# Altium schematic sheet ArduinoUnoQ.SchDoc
size A4; SheetNumber: 1; SheetTotal: 1
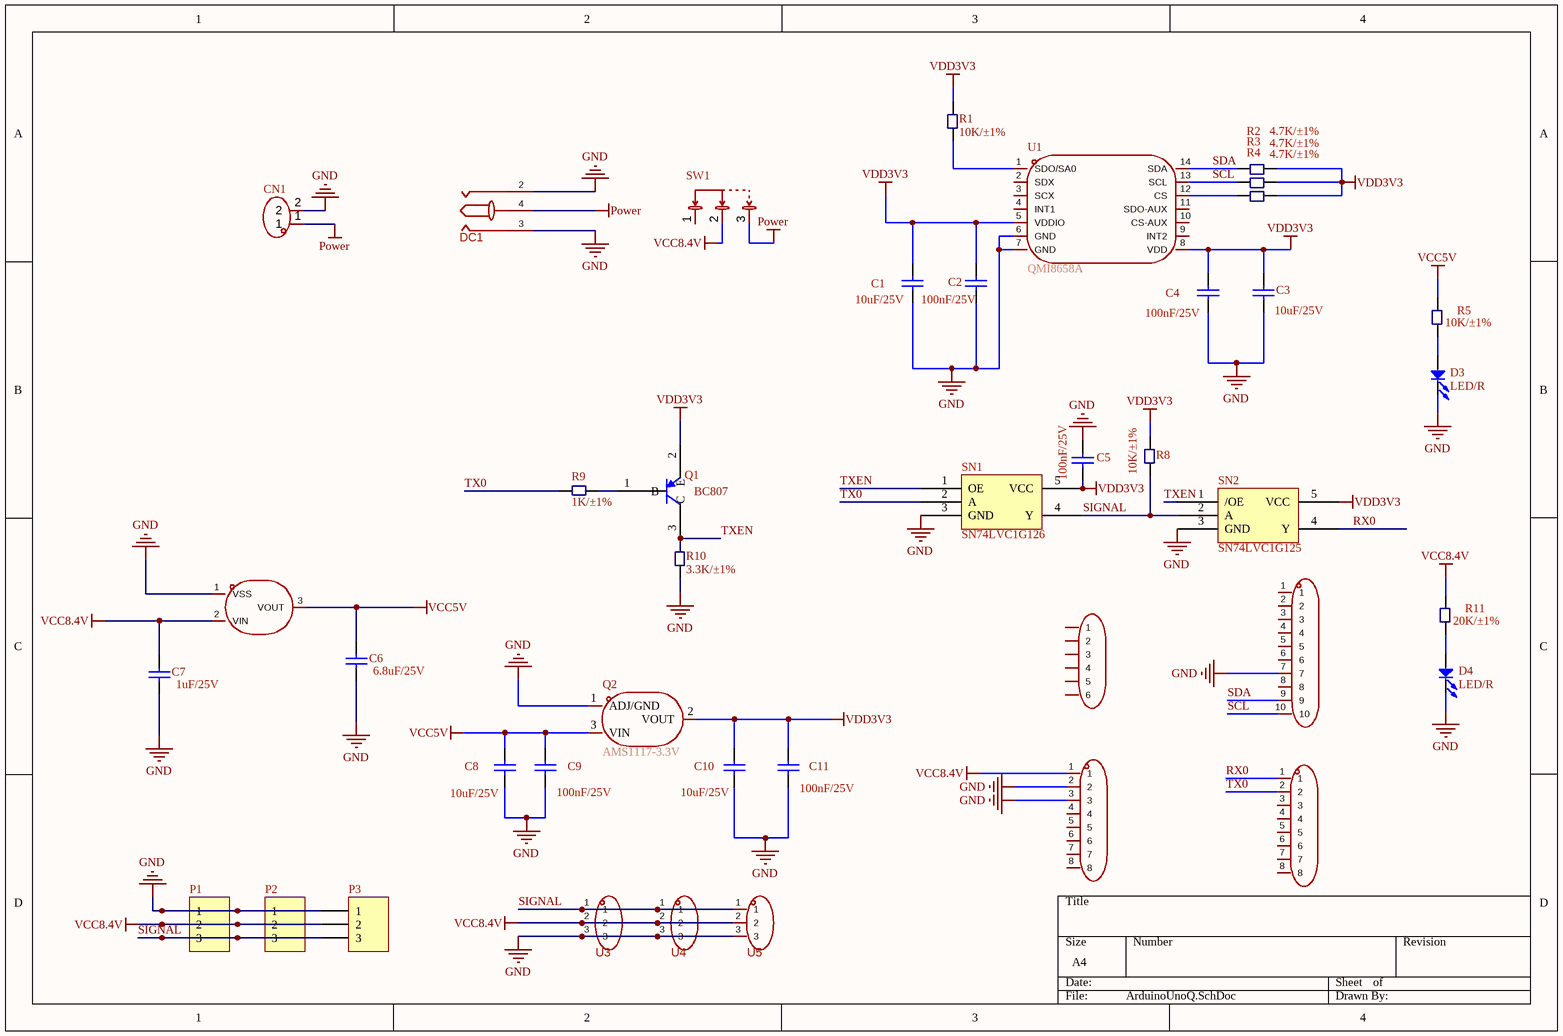
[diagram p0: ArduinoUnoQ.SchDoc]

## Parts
C1  10uF/25V  [C0603]
C2  100nF/25V  [C0603]
C3  10uF/25V  [C0603]
C4  100nF/25V  [C0603]
C5  100nF/25V  [C0603]
C6  6.8uF/25V  [C0603]
C7  1uF/25V  [C0603]
C8  10uF/25V  [C0603]
C9  100nF/25V  [C0603]
C10  10uF/25V  [C0603]
C11  100nF/25V  [C0603]
CN1  ZX-XH2.54-2PWZ  [CONN-TH_2P-P2.50_ZX-XH2.54-2PWZ]  (value not drawn)
D3  LED/R  [D_SOD_523]
D4  LED/R  [D_SOD_523]
DC1  kh-dc-007b-2.1g  [DC-IN-TH_KH-DC-007B-2.1G]  (value not drawn)
H1  pz254v-11-06p  [HDR-TH_6P-P2.54-V-M]  (value not drawn)
H2  pz254v-11-10p  [HDR-TH_10P-P2.54-V-M]  (value not drawn)
H3  pz254v-11-08p  [HDR-TH_8P-P2.54-V-M]  (value not drawn)
H4  pz254v-11-08p  [HDR-TH_8P-P2.54-V-M]  (value not drawn)
P1  mx1.25 1*3P  [MX 1.25-WI-3P]  (value not drawn)
P2  mx1.25 1*3P  [MX 1.25-WI-3P]  (value not drawn)
P3  mx1.25 1*3P  [MX 1.25-WI-3P]  (value not drawn)
Q1  BC807  [SOT-23-3]
Q2  AMS1117-3.3V  [SOT-89-3_L4.5-W2.5-P1.50-LS4.2-BR]
R1  10K/±1%  [R0603]
R2  4.7K/±1%  [R0603]
R3  4.7K/±1%  [R0603]
R4  4.7K/±1%  [R0603]
R5  10K/±1%  [R0603]
R8  10K/±1%  [R0603]
R9  1K/±1%  [R0603]
R10  3.3K/±1%  [R0603]
R11  20K/±1%  [R0603]
SN1  SN74LVC1G126  [SOT_23_5]
SN2  SN74LVC1G125  [SOT_23_5]
SW1  SS-12D06L5  [SW-TH_3P-P4.70_L11.1-W12.7]  (value not drawn)
U1  QMI8658A  [LGA-14_L3.0-W2.5-P0.50-TL]
U2  HT7550-1  [SOT-89-3_L4.5-W2.5-P1.50-LS4.2-BR]  (value not drawn)
U3  292253-3  [CONN-TH_3P-P2.00_TE_292253-3]  (value not drawn)
U4  292253-3  [CONN-TH_3P-P2.00_TE_292253-3]  (value not drawn)
U5  292253-3  [CONN-TH_3P-P2.00_TE_292253-3]  (value not drawn)

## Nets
GND: C1.1 C2.1 C3.1 C4.1 C5.2 C6.1 C7.1 C8.1 C9.1 C10.1 C11.1 CN1.2 D3.2(K) D4.2(K) DC1.2 DC1.3 H2.7 H3.2 H3.3 P1.1 P2.1 P3.1 Q2.1(ADJ/GND) R10.2 SN1.3(GND) SN2.3(GND) U1.6(GND) U1.7(GND) U2.1(VSS) U3.3 U4.3 U5.3
Power: CN1.1 DC1.4 SW1.3
VCC5V: C6.2 C8.2 C9.2 Q2.3(VIN) R5.1 U2.3(VOUT)
VCC8.4V: C7.2 H3.1 P1.2 P2.2 P3.2 R11.1 SW1.2 U2.2(VIN) U3.2 U4.2 U5.2
VDD3V3: C1.2 C2.2 C3.2 C4.2 C5.1 C10.2 C11.2 Q1.2(E) Q2.2(VOUT) R1.1 R2.2 R3.2 R4.2 R8.1 SN1.5(VCC) SN2.5(VCC) U1.5(VDDIO) U1.8(VDD)
RX0: H4.1 SN2.4(Y)
SCL: H2.10 R3.1 U1.13(SCL)
SDA: H2.9 R2.1 U1.14(SDA)
SIGNAL: P1.3 P2.3 P3.3 R8.2 SN1.4(Y) SN2.2(A) U3.1 U4.1 U5.1
TX0: H4.2 R9.2 SN1.2(A)
TXEN: Q1.3(C) R10.1 SN1.1(OE) SN2.1(/OE)
NetD3_1: D3.1(A) R5.2
NetD4_1: D4.1(A) R11.2
NetQ1_1: Q1.1(B) R9.1
NetR1_2: R1.2 U1.1(SDO/SA0)
NetR4_1: R4.1 U1.12(CS)

Not connected (* = marked no-connect by the designer): H1 1 2 3 4 5 6; H2 1 2 3 4 5 6 8; H3 4 5 6 7 8; H4 3 4 5 6 7 8; SW1 1; U1 2(SDX) 3(SCX) 4(INT1) 9(INT2) 10(CS-AUX) 11(SDO-AUX)

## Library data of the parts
C1-C4 C6-C11 = 0603 C: 0603贴片电容，±10%，50V
C5 = 0603 10nF (103) 10% 50V: 0603贴片电容，±10%，50V
CN1 = ZX-XH2.54-2PWZ: 插针结构:1x2P;间距:2.5mm;安装方式:弯插;参考系列:XH;总PIN数:2P;排数:1;每排PIN数:2;行距:-;额定电流:2A;触头材质:黄铜;触头镀层:锡;工作温度:-25℃~+85℃;; Manufacturer: Megastar(兆星); AddInBom: yes; ModelId: 24f25f0d7a3348c685f49f501f04732c聨0819f05c4eef4c71ace90d822a990e87; ModelTransform: 295.669,300.7868,0,0,0,0,0,-137.795,-133.858; Pins Structure: 1x2P; Pitch: 2.5mm; Reference Series: XH; Number of PINs Per Row: 2; Current Rating: 2A; Voltage Rating: 250V; Plastic Material: PA66; Flame Retardant Rating: UL94V-0; Z-Height of the Board: 5.9mm; X-Length of Bottom Edge on Board (Spacing Line): 7.5mm; Y-Width of Bottom Edge on Board: 7.32mm
D3 D4 = LED: Typical INFRARED GaAs LED
DC1 = kh-dc-007b-2.1g: 连接器类型:DC电源插座;安装方式:弯插;触点内径:-;触点外径:-;额定电流:3A;额定电压:50V;工作温度:-30℃~+70℃;; Manufacturer: kinghelm(金航标); AddInBom: yes; ModelId: db467a4a132a497c9fa96d37cafb49be; ModelTransform: 511.81,393.7,0,270,0,0,0,90.551,-74.803; Connector Type: DC电源插座; Current Rating: 3A; Voltage Rating (Max): 50V; Body Height: 10mm
H1 = pz254v-11-06p: 插针结构:1x6P;间距:2.54mm;行距:-;圆针/方针:方针;安装方式:直插;排数:单排;总PIN位数:6P;额定电流:3A;额定电压:-;配合针长度:6mm;塑高:2.5mm;端接针长度:3mm;触头材质:黄铜;触头镀层:金;工作温度:-40℃~+105℃;颜色:黑色;; Manufacturer: BOOMELE(博穆精密); ManufacturerPart: 2.54-1x6P直针; Symbol: Header-Male-2.54_1x6; AddInBom: yes; ModelId: 60739dffc9b04830a286435b0fefbd4a; ModelName: HDR2.54-M-LI-1X6P; ModelTransform: 599.999,100,0,0,0,0,0,0,-118.11; Pin Structure: 1x6P; Pitch: 2.54mm; Circluar Pins/Square Pins: 方针; Current Rating: 3A
H2 = pz254v-11-10p: 插针结构:1x10P;间距:2.54mm;行距:-;圆针/方针:方针;安装方式:直插;排数:单排;总PIN位数:10P;额定电流:3A;额定电压:250V;配合针长度:6mm;塑高:2.5mm;端接针长度:3mm;触头材质:黄铜;触头镀层:-;工作温度:-40℃~+105℃;颜色:黑色;; Manufacturer: XFCN(兴飞); AddInBom: yes; ModelId: 10f3d1cea59e4bb4ba116af9f09c2b9b; ModelName: HDR2.54-M-LI-1X10P; ModelTransform: 999.99796,100,0,0,0,0,0,0,-118.11; Pin Structure: 1x10P; Pitch: 2.54mm; Circluar Pins/Square Pins: 方针; Current Rating: 3A; Voltage Rating (Max): 250V
H3 H4 = pz254v-11-08p: 插针结构:1x8P;间距:2.54mm;行距:-;圆针/方针:方针;安装方式:直插;排数:单排;总PIN位数:8P;额定电流:3A;额定电压:250V;配合针长度:6mm;塑高:2.5mm;端接针长度:3mm;触头材质:黄铜;触头镀层:-;工作温度:-40℃~+105℃;颜色:黑色;; Manufacturer: XFCN(兴飞); AddInBom: yes; ModelId: f5b96e27511e49e38545e53df2320202; ModelTransform: 807.87244,98.425,0,0,0,0,0,0,-118.11; Pin Structure: 1x8P; Pitch: 2.54mm; Circluar Pins/Square Pins: 方针; Current Rating: 3A; Voltage Rating (Max): 250V
P1-P3 = Header 3: 1x3P 间距:1.25mm 直插
Q1 = PNP 60V 600mA: hfe=250~600 PNP 电流:500mA 电压:45V
Q2 = AMS1117-3.3V_SOT89: 输入18V 输出3.3V 1A，SOT-89封装; Manufacturer: MSKSEMI(美森科); Symbol: AMS1117-3.3V_C5120796; Add into BOM: yes; Output Type: 固定; Voltage - Supply: 18V; Output Voltage: 3.3V; Output Current: 1A; Voltage Dropout: 1.4V@(1A); standby current: 12mA; Output Configuration: 正极; Number of Outputs: 1
R1-R5 R8 R10 R11 = Res2_1: 厚膜电阻  ±1% 100mW
R9 = Res2_1: 厚膜电阻 ±1% 100mW
SN1 = SN74LVC1G126: 三态输出，单路总线缓冲门
SN2 = SN74LVC1G125: 单总线缓冲门，带三态输出
SW1 = SS-12D06L5: 电路结构:单刀双掷;安装方式:-;开关颜色:黑色;额定电流:3A;额定电压:125V;工作寿命:1万次;; Manufacturer: XKB Connection(中国星坤); AddInBom: yes; ModelId: cdc951e5f4794e0cacc9ea6ffda3ed7a聨0819f05c4eef4c71ace90d822a990e87; ModelTransform: 509.842,582.67596,0,0,0,0,0,-265.748,-145.669; Circuit: 单刀双掷; Actuator Style: 矩形柱状; Switch Height: 6.3mm; Actuator Color: 黑色; Current Rating: 3A; Voltage Rating: 125V; Life: 1万次
U1 = QMI8658A: 六轴陀螺仪  陀螺仪量程(MAX) ±2048dps  加速度计量程(MAX) ±16g; Symbol: QMI8658A_C3021082
U2 = HT7550-1: 线性稳压器(LDO),5V 150mA 30V; Manufacturer: HOLTEK(合泰/盛群); AddInBom: yes; ModelId: 6db690b7897d4d18a30d90c1b89525ee; ModelName: SOT-89-3_L4.3-W2.5-H1.6-LS4.1-P1.50; ModelTransform: 161.417,169.291,0,180,0,0,-18.661,0,0; Output Configuration: 正极; Voltage - Supply: 8.5V; Output Current: 1A; Voltage Dropout: 50mV@(100mA); standby current: 2uA; Output Type: 固定; Number of Outputs: 1
U3-U5 = 292253-3: 插针结构:1x3P;间距:2mm;安装方式:弯插;总PIN数:3P;排数:1;每排PIN数:3;额定电流:4A;触头材质:黄铜;触头镀层:锡;工作温度:-40℃~+105℃;; Manufacturer: TE Connectivity(泰科电子); AddInBom: yes; ModelId: a9520a19719f44d590017de8a7a53ae9; ModelTransform: 307.086,346.456,0,0,0,0,-11.81,-106.299,-125.984; Pins Structure: 1x3P; Pitch: 2mm; Number of PINs Per Row: 3; Current Rating: 4A; Voltage Rating: 125V; Plastic Material: PA66; Flame Retardant Rating: UL94V-0; Z-Height of the Board: 4mm; X-Length of Bottom Edge on Board (Spacing Line): 7.8mm; Y-Width of Bottom Edge on Board: 8.8mm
